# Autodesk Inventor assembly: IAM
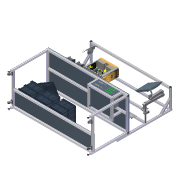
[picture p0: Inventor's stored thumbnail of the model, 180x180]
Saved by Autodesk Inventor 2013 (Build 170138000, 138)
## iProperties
Created: 2012-10
Part Number: IAM
Document SubType Name: Assembly
Designer: Administrator
Author: Administrator
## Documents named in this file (3)
- C:\_ARBEIT\Dropbox\_privat\01_Arbeit\FAQ\inventorfaq.blogspot.com\IVBENCH\_DATEN\IAM.iam
- C:\_ARBEIT\Dropbox\_privat\01_Arbeit\FAQ\inventorfaq.blogspot.com\IVBENCH\_DATEN\Test Station\Test Station.iam
- C:\_ARBEIT\Dropbox\_privat\01_Arbeit\FAQ\inventorfaq.blogspot.com\IVBENCH\_DATEN\Personal Computer\Personal Computer.iam
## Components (2 placed, 2 different names)
1. Test Station:1 [sub-assembly] — Passend:1, Fluchtend:1
2. Personal Computer:1 [sub-assembly] — Passend:1, Fluchtend:1
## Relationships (2: Mate 1, Flush 1)
- Passend:1 [Mate]: Test Station:1 ↔ Personal Computer:1
- Fluchtend:1 [Flush]: Test Station:1 ↔ Personal Computer:1
